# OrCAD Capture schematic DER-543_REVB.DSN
size Custom
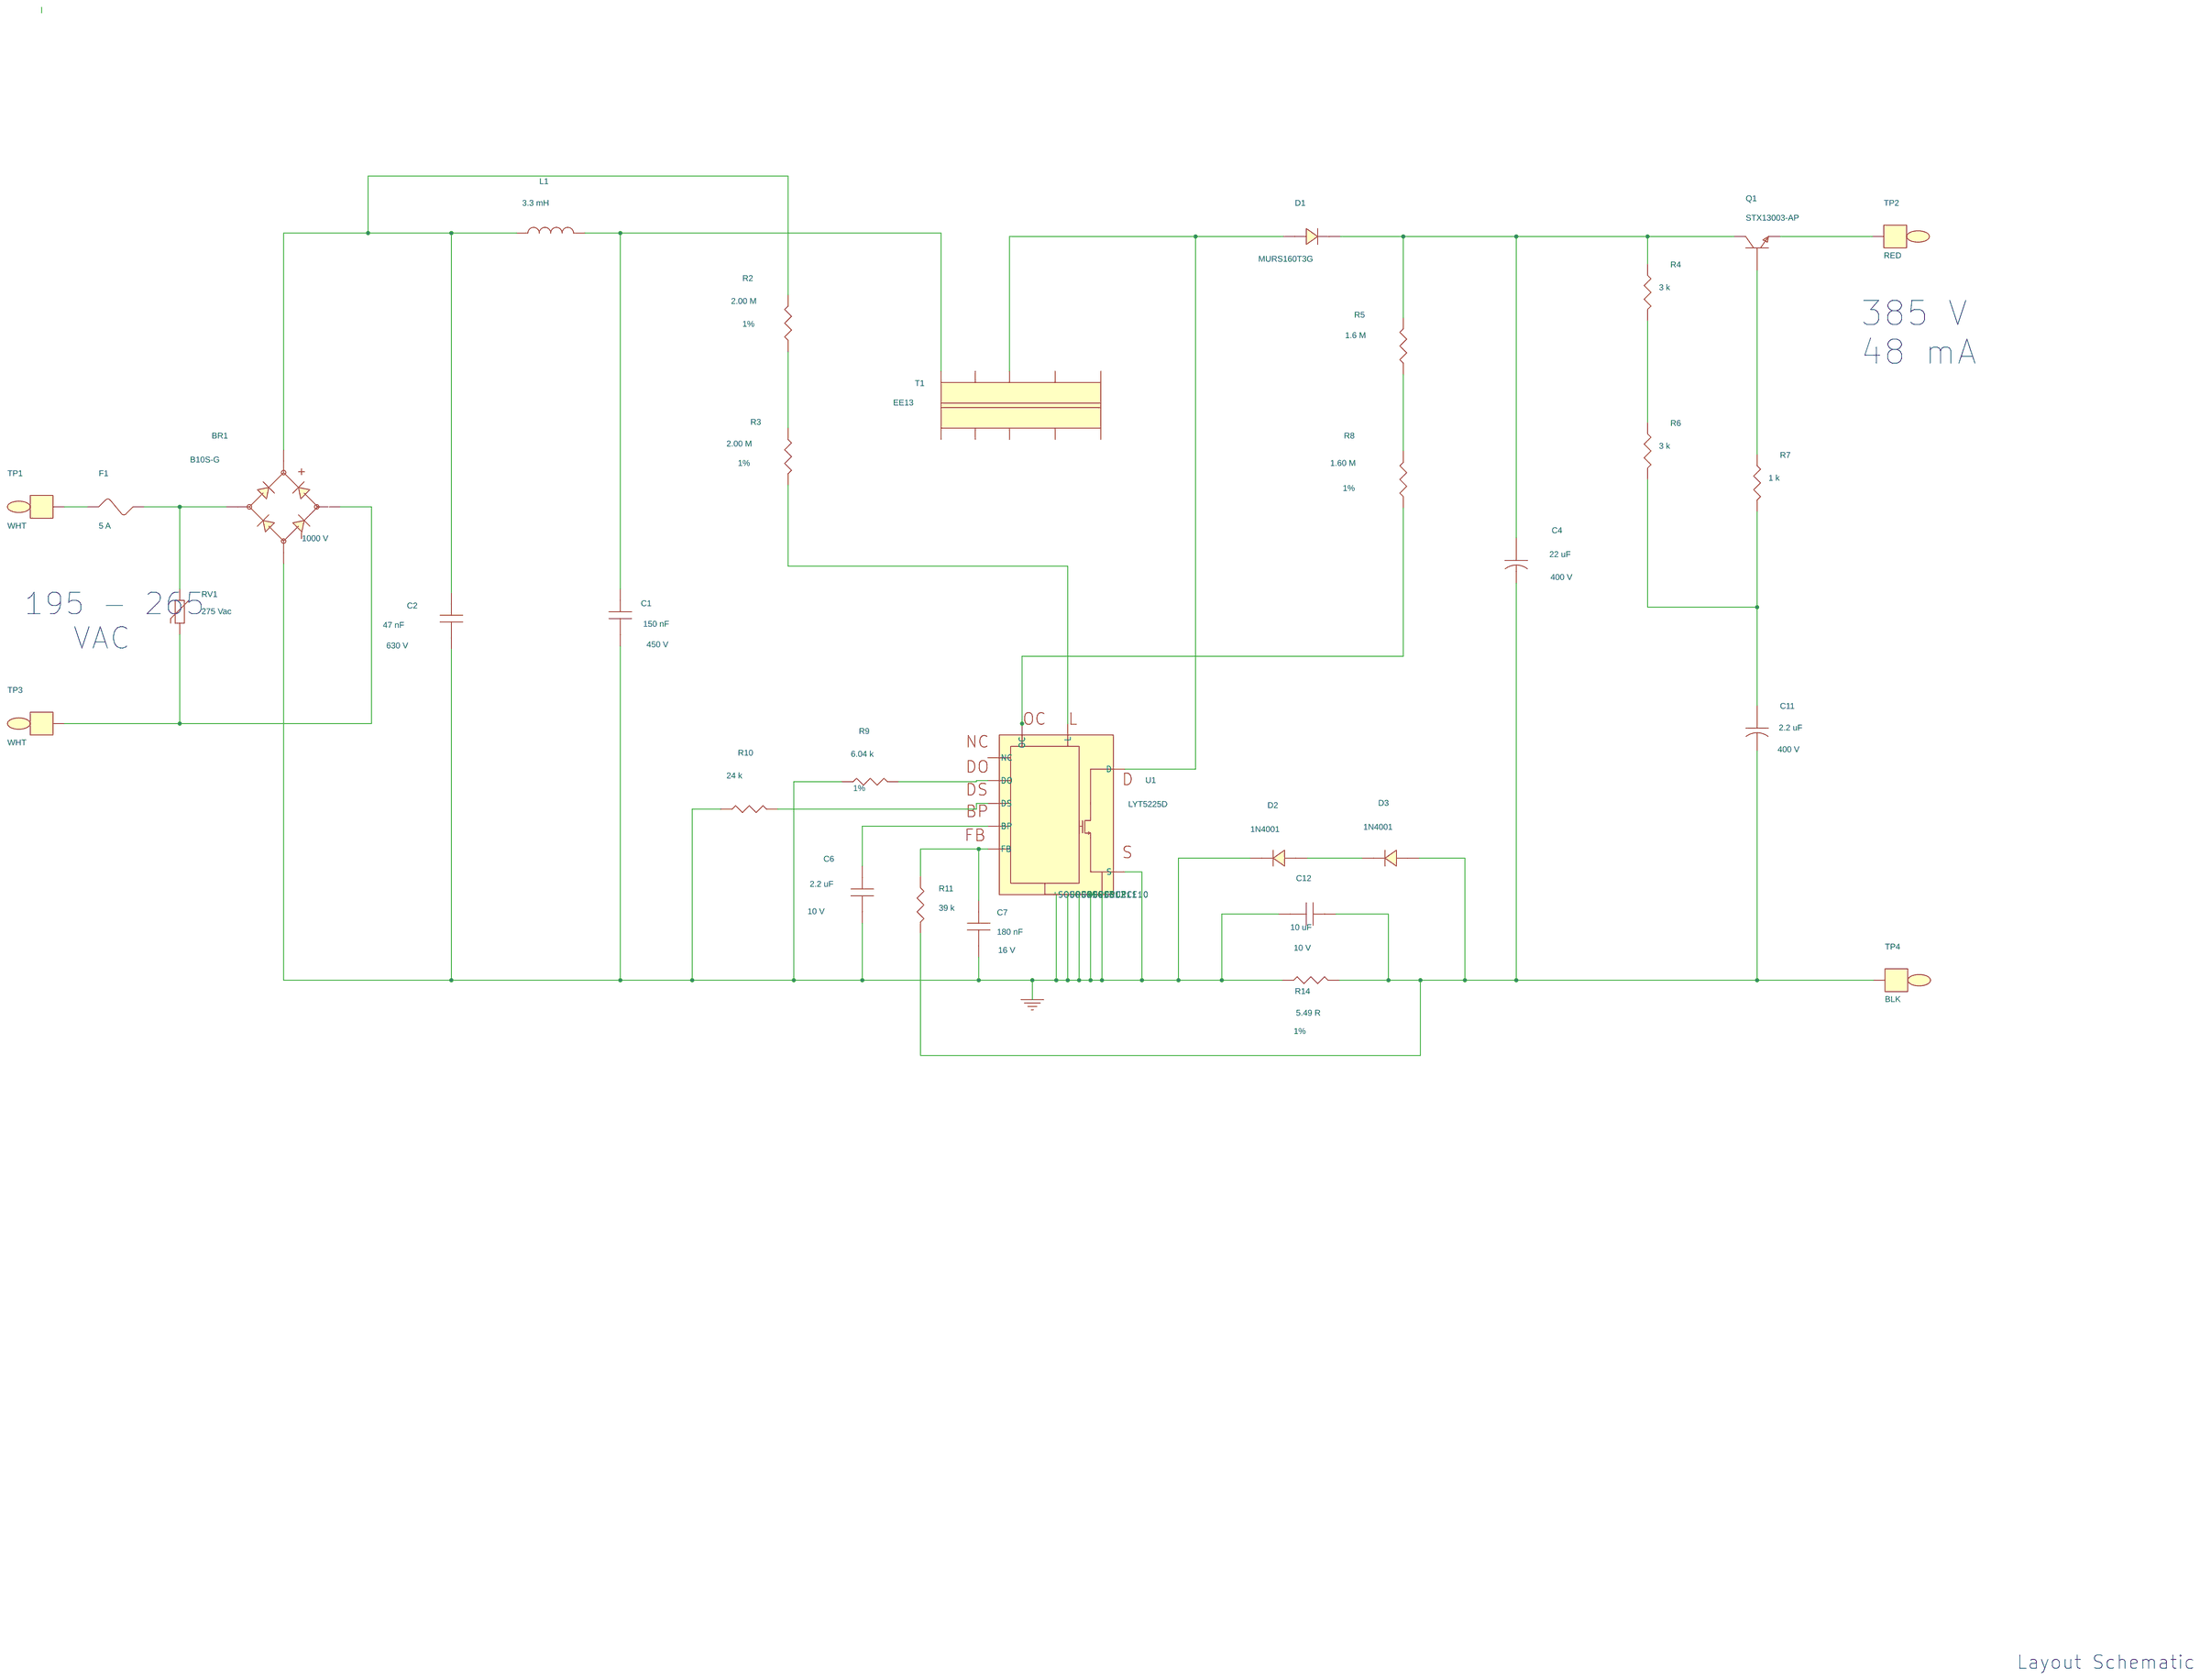
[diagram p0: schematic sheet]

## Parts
BR1  B10S-G  [pismsoic4]
C1  150 nF  [pinpcaprad500x200400040]
C2  47 nF  [PI_NP395X200LS300D040]
C4  22 uF  [pipolcapclyd500ls200040]
C6  2.2 uF  [pismc0603]
C7  180 nF  [pismc0603]
C11  2.2 uF  [pipolcapcyld250ls100030]
C12  10 uF  [pismc0805]
D1  MURS160T3G  [pismsmb]
D2  1N4001  [pidv200x110x040do41]
D3  1N4001  [pidv200x110x040do41]
F1  5 A  [pi_v_axial_160ls150d030]
L1  3.3 mH  [pichoke030dials200035]
Q1  STX13003-AP  [PITO92R100]
R2  2.00 M  [pismr1206]
R3  2.00 M  [pismr1206]
R4  3 k  [pismr1206]
R5  1.6 M  [pi14wvresd100ls100d030]
R6  3 k  [pismr1206]
R7  1 k  [pismr0805]
R8  1.60 M  [pismr1206]
R9  6.04 k  [pismr0603]
R10  24 k  [pismr0603]
R11  39 k  [pi18wvresd80ls100d030]
R14  5.49 R  [pismr1206]
RV1  275 Vac  [pidisc350x160ls210x140040]
T1  EE13  [pi_bobbin_ee13v_10p]
TP1  WHT  [pitpkeystone100x100]
TP2  RED  [pitpkeystone100x100]
TP3  WHT  [pitpkeystone100x100]
TP4  BLK  [pitpkeystone100x100]
U1  LYT5225D  [pi_smd_so_14-16p_short9-14]

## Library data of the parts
BR1 = DIODE_BRIDGE_~~+-: ALT_SYMBOLS: pi_sm_soic4_slot; Disp_Voltage: 1000 V; FPLIST: pismsoic4,pi_sm_soic4_slot; Part Number: 15-00818-00
C1 = CAP_NP: Disp_Voltage: 450 V; Part Number: 20-08944-00; Voltage: 450 V
C2 = CAP_NP: Disp_Voltage: 630 V; Part Number: 20-08702-00; Voltage: 630 V
C4 = CAP_POL: ALT_SYMBOLS: pipolcapclyd500ls200040630lh; Disp_Voltage: 400 V; FPLIST: pipolcapclyd500ls200040,pipolcapclyd500ls200040630lh; Part Number: 20-08737-00; Voltage: 400 V
C6 = CAP_NP: Disp_Voltage: 10 V; Part Number: 20-08740-00; Voltage: 10V
C7 = CAP_NP: Disp_Voltage: 16 V; Part Number: 20-08711-00; Voltage: 16V
C11 = CAP_POL: ALT_SYMBOLS: pipolcapcyld250ls100030h; Disp_Voltage: 400 V; FPLIST: pipolcapcyld250ls100030,pipolcapcyld250ls100030h; Part Number: 20-01008-00; Voltage: 400 V
C12 = CAP_NP: Disp_Voltage: 10 V; Part Number: 20-01021-00; Voltage: 10 V
D1 = DIODE: Part Number: 15-00487-00
D2 D3 = DIODE: ALT_SYMBOLS: pidax475x125040do41,pidv200x110x040do41wbead,pidax390x125040do41; FPLIST: pidv200x110x040do41,pidax475x125040do41,pidv200x110x040do41wbead,pidax390x125040do41; Part Number: 15-01169-00
F1 = FUSE: FPLIST: pi_v_axial_160ls150d030,pi_v_axial_160ls250d030,pi12wvresd180ls200d040; Part Number: 40-00026-00
L1 = INDUCTOR: ALT_SYMBOLS: pi_choke_450hx375ls197d030_h; Part Number: 30-00168-00
Q1 = NPN_ECB: ALT_SYMBOLS: PIT092100; FPLIST: PITO92R100,PIT092100; Part Number: 55-00110-00
R2 R3 = R: Disp_Tol: 1%; Part Number: 05-03156-00
R4 R6 = R: Part Number: 05-01363-00
R5 = R: ALT_SYMBOLS: pi14wvresd100ls200d030,pi14wresd100ls400d030,pi14wresd100ls500d030; FPLIST: pi14wvresd100ls100d030,pi14wvresd100ls200d030,pi14wresd100ls400d030,pi14wresd100ls500d030; Part Number: 05-03108-00
R7 = R: Part Number: 05-01519-00
R8 = R: Disp_Tol: 1%; Part Number: 05-03154-00
R9 = R: Disp_Tol: 1%; Part Number: 05-01153-00
R10 = R: Part Number: 05-01721-00
R11 = R: ALT_SYMBOLS: pi18wresd080ls300d030; Disp_Power: 0.125 W; FPLIST: pi18wvresd80ls100d030,pi18wresd080ls300d030; Part Number: 05-02375-00
R14 = R: Disp_Power: 0.25 W; Disp_Tol: 1%; Part Number: 05-06385-00
RV1 = VARISTOR: FPLIST: pidisc350x160ls210x140040,pi_disc_354x220_ls220x10_040_h; Part Number: 85-00015-00
T1 = BEE13_10PINS_GENERIC: Part Number: 25-01023-00
TP1 TP3 = TESTPOINT: Part Number: 35-00081-00
TP2 = TESTPOINT: Part Number: 35-00080-00
TP4 = TESTPOINT: Part Number: 35-00079-00
U1 = LYTSW-5_SO-16: Part Number: 10-00972-00

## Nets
GND: BR1.4 C1.2 C2.2 C6.2 C7.2 C12.2 D2.1 R9.2 R10.2 R14.1 U1.9(S) U1.10(SOURCE10) U1.11(SOURCE11) U1.12(SOURCE12) U1.13(SOURCE13) U1.14(SOURCE14)
N3973903: BR1.2 RV1.2 TP3.1
N3973993: BR1.3 C2.1 L1.1 R2.1
N3974133: C4.1 D1.1 Q1.2(COLLECTOR) R4.1 R5.1
N3975245: C1.1 L1.2 T1.10
N3976866: F1.2 TP1.1
N3988573: C7.1 R11.1 U1.1(FB)
N3988655: R10.1 U1.4(DS)
N3988764: R9.1 U1.3(DO)
N4093437: BR1.1 F1.1 RV1.1
N4116147: C6.1 U1.15(BP)
N4143937: R2.2 R3.1
N4145625: R3.2 U1.2(L)
N4152865: D1.2 T1.8 U1.8(D)
N4154298: C4.2 C11.2 C12.1 D3.2 R11.2 R14.2 TP4.1
N4154621: R8.2 U1.16(OC)
N4279554: Q1.1(EMITTER) TP2.1
N4283675: C11.1 R6.2 R7.2
N4283879: Q1.3(BASE) R7.1
N4293995: D2.2 D3.1
N4302369: R4.2 R6.1
N4302480: R5.2 R8.1

Not connected (* = marked no-connect by the designer): T1 1 2 3 4 5 6 7 9; U1 5(NC)

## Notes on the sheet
- 385 V
  48 mA
- 195 - 265
     VAC
- Layout Schematic
